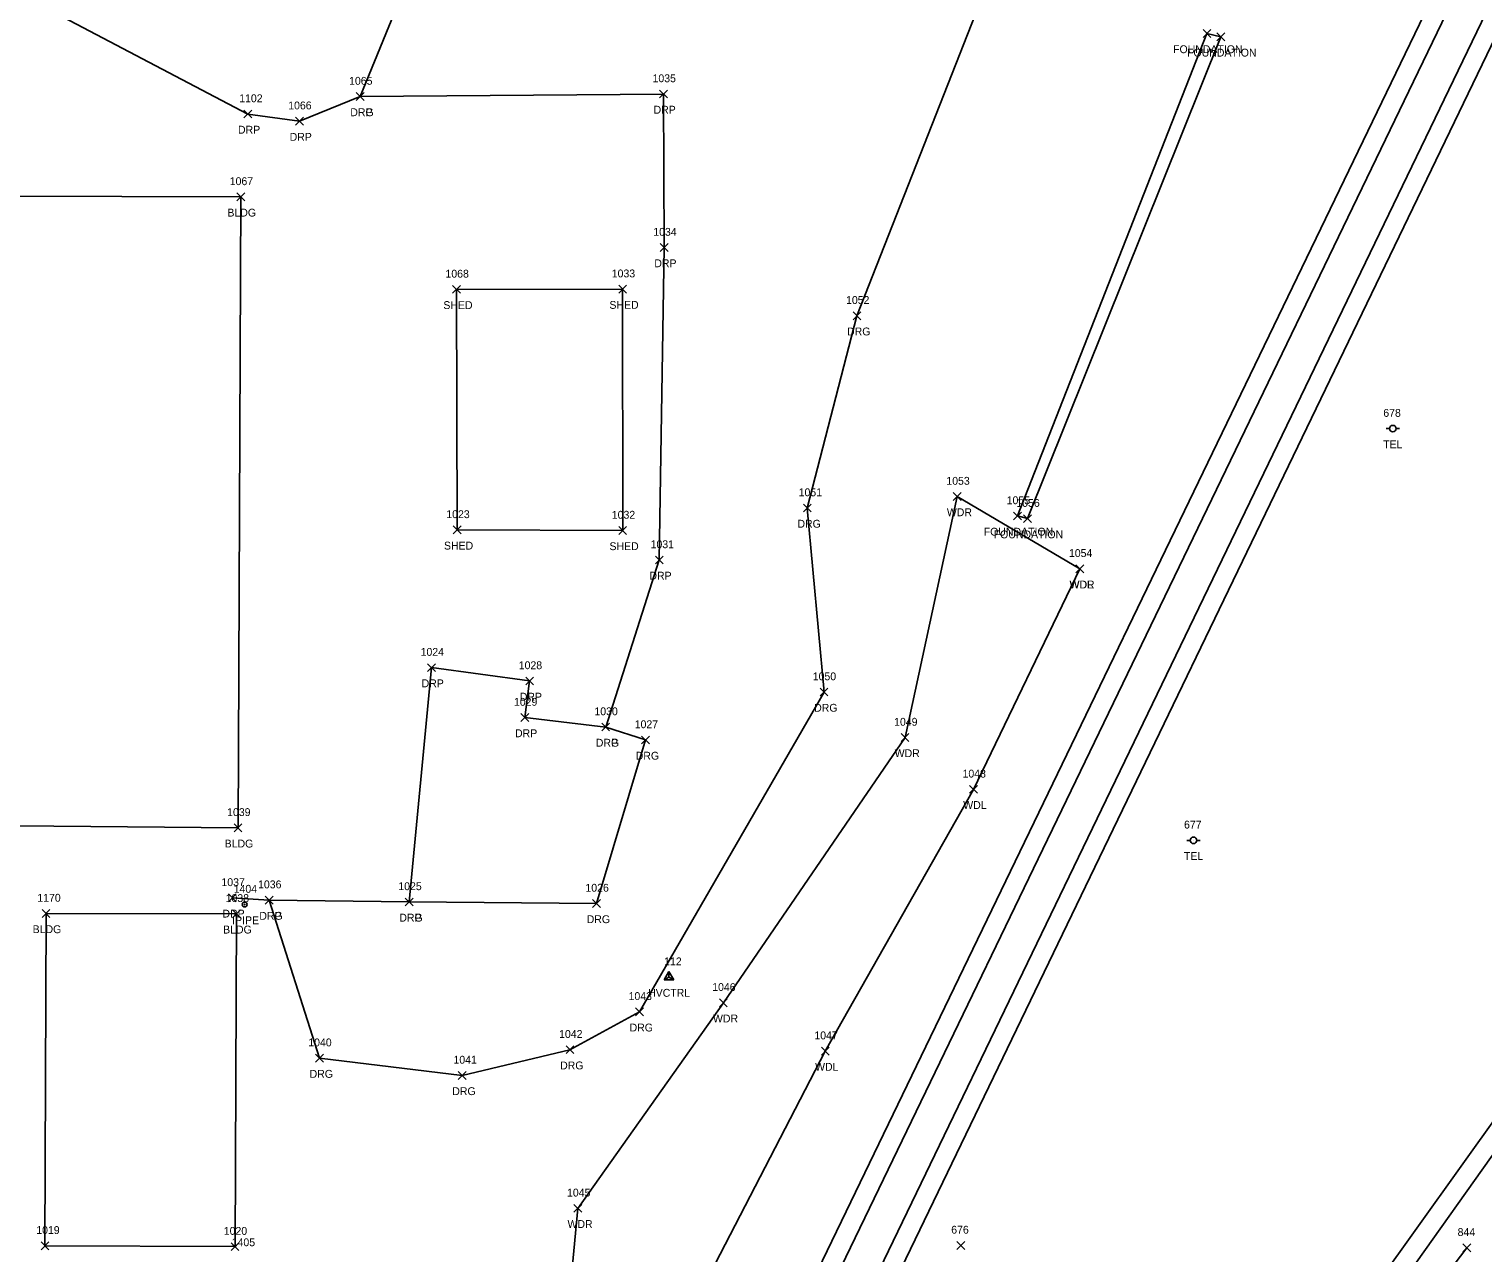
# Model space of a CAD drawing. Extents: x 1767353 to 1772625, y 740790 to 747702.
# Drawn here: x 1770255.6 to 1770625.6, y 742669.5 to 742981 of the extents above; entities that cross this region are included whole.
import ezdxf

# ---------------------------------------------------------------- set-up
doc = ezdxf.new("R2010")
doc.units = 0
for name, color, linetype in [('C_A', 7, 'Continuous'), ('C_I', 7, 'Continuous'), ('CPSM', 7, 'Continuous'), ('L_A', 7, 'Continuous'), ('L_I', 7, 'Continuous'), ('L_TIC', 7, 'Continuous'), ('LAWA', 7, 'Continuous'), ('LBC', 7, 'Continuous'), ('M_A', 7, 'Continuous'), ('M_I', 7, 'Continuous'), ('MPIP', 7, 'Continuous'), ('R_A', 7, 'Continuous'), ('R_I', 7, 'Continuous'), ('R_TIC', 7, 'Continuous'), ('RDG', 7, 'Continuous'), ('RDP', 7, 'Continuous'), ('RR', 7, 'Continuous'), ('U_A', 7, 'Continuous'), ('U_I', 7, 'Continuous'), ('UP', 7, 'Continuous')]:
    doc.layers.add(name, color=color, linetype=linetype)

msp = doc.modelspace()

# ---------------------------------------------------------------- linework, layer by layer
at = {"layer": 'CPSM'}
for p, q in [((1770417.21, 742738.98), (1770418.46, 742741.14)), ((1770417.21, 742738.98), (1770418.46, 742739.7)), ((1770419.71, 742738.98), (1770418.46, 742741.14)), ((1770418.46, 742739.7), (1770418.46, 742741.14)), ((1770418.46, 742739.7), (1770418.46, 742739.7)), ((1770418.46, 742739.7), (1770419.71, 742738.98)), ((1770417.21, 742738.98), (1770419.71, 742738.98))]:
    msp.add_line(p, q, dxfattribs=at)
at = {"layer": 'L_TIC'}
for points in [[(1770554.38, 742978.86), (1770556.38, 742980.86)], [(1770556.38, 742978.86), (1770554.38, 742980.86)], [(1770557.94, 742977.99), (1770559.94, 742979.99)], [(1770559.94, 742977.99), (1770557.94, 742979.99)], [(1770308.49, 742937.27), (1770310.49, 742939.27)], [(1770310.49, 742937.27), (1770308.49, 742939.27)], [(1770363.4, 742913.73), (1770365.4, 742915.73)], [(1770365.4, 742913.73), (1770363.4, 742915.73)], [(1770405.67, 742913.79), (1770407.67, 742915.79)], [(1770407.67, 742913.79), (1770405.67, 742915.79)], [(1770490.83, 742861.01), (1770492.83, 742863.01)], [(1770492.83, 742861.01), (1770490.83, 742863.01)], [(1770506.18, 742856.06), (1770508.18, 742858.06)], [(1770508.18, 742856.06), (1770506.18, 742858.06)], [(1770363.56, 742852.52), (1770365.56, 742854.52)], [(1770365.56, 742852.52), (1770363.56, 742854.52)], [(1770405.68, 742852.37), (1770407.68, 742854.37)], [(1770407.68, 742852.37), (1770405.68, 742854.37)], [(1770508.71, 742855.38), (1770510.71, 742857.38)], [(1770510.71, 742855.38), (1770508.71, 742857.38)], [(1770522.03, 742842.62), (1770524.03, 742844.62)], [(1770524.03, 742842.62), (1770522.03, 742844.62)], [(1770522.03, 742842.62), (1770524.03, 742844.62)], [(1770524.03, 742842.62), (1770522.03, 742844.62)], [(1770477.55, 742799.68), (1770479.55, 742801.68)], [(1770479.55, 742799.68), (1770477.55, 742801.68)], [(1770494.95, 742786.49), (1770496.95, 742788.49)], [(1770496.95, 742786.49), (1770494.95, 742788.49)], [(1770307.79, 742776.69), (1770309.79, 742778.69)], [(1770309.79, 742776.69), (1770307.79, 742778.69)], [(1770258.92, 742754.89), (1770260.92, 742756.89)], [(1770260.92, 742754.89), (1770258.92, 742756.89)], [(1770307.4, 742754.8), (1770309.4, 742756.8)], [(1770309.4, 742754.8), (1770307.4, 742756.8)], [(1770431.3, 742732.17), (1770433.3, 742734.17)], [(1770433.3, 742732.17), (1770431.3, 742734.17)], [(1770457.24, 742719.87), (1770459.24, 742721.87)], [(1770459.24, 742719.87), (1770457.24, 742721.87)], [(1770394.28, 742679.85), (1770396.28, 742681.85)], [(1770396.28, 742679.85), (1770394.28, 742681.85)], [(1770258.64, 742670.32), (1770260.64, 742672.32)], [(1770260.64, 742670.32), (1770258.64, 742672.32)], [(1770307.02, 742670.11), (1770309.02, 742672.11)], [(1770309.02, 742670.11), (1770307.02, 742672.11)], [(1770491.76, 742670.41), (1770493.76, 742672.41)], [(1770493.76, 742670.41), (1770491.76, 742672.41)], [(1770620.54, 742669.81), (1770622.54, 742671.81)], [(1770622.54, 742669.81), (1770620.54, 742671.81)]]:
    msp.add_lwpolyline(points, dxfattribs=at)
at = {"layer": 'LAWA'}
for points in [[(1770306.48, 742507.29), (1770316.18, 742614.11), (1770369.05, 742611.22), (1770392.48, 742651.21), (1770395.28, 742680.85), (1770432.3, 742733.17), (1770478.55, 742800.68), (1770491.83, 742862.01), (1770523.03, 742843.62)], [(1770306.48, 742507.29), (1770329.16, 742496.59), (1770362.8, 742536.32), (1770458.24, 742720.87), (1770495.95, 742787.49), (1770523.03, 742843.62)]]:
    msp.add_lwpolyline(points, dxfattribs=at)
at = {"layer": 'LBC'}
for points in [[(1770507.18, 742857.06), (1770509.71, 742856.38), (1770558.94, 742978.99), (1770555.38, 742979.86)], [(1770555.38, 742979.86), (1770507.18, 742857.06)], [(1770309.49, 742938.27), (1770248.94, 742938.42)], [(1770308.79, 742777.69), (1770309.49, 742938.27)], [(1770364.56, 742853.52), (1770406.68, 742853.37), (1770406.67, 742914.79), (1770364.4, 742914.73)], [(1770364.4, 742914.73), (1770364.56, 742853.52)], [(1770224.34, 742778.43), (1770308.79, 742777.69)], [(1770259.92, 742755.89), (1770259.64, 742671.32)], [(1770259.64, 742671.32), (1770308.02, 742671.11), (1770308.4, 742755.8)], [(1770308.4, 742755.8), (1770259.92, 742755.89)], [(1770582.39, 742619.29), (1770621.54, 742670.81)]]:
    msp.add_lwpolyline(points, dxfattribs=at)
at = {"layer": 'MPIP'}
for radius in [0.625, 0.0833]:
    msp.add_circle((1770310.46, 742758.17), radius, dxfattribs=at)
at = {"layer": 'R_TIC'}
for points in [[(1770416.05, 742963.46), (1770418.05, 742965.46)], [(1770418.05, 742963.46), (1770416.05, 742965.46)], [(1770338.87, 742962.82), (1770340.87, 742964.82)], [(1770340.87, 742962.82), (1770338.87, 742964.82)], [(1770338.87, 742962.82), (1770340.87, 742964.82)], [(1770340.87, 742962.82), (1770338.87, 742964.82)], [(1770310.28, 742958.37), (1770312.28, 742960.37)], [(1770312.28, 742958.37), (1770310.28, 742960.37)], [(1770323.43, 742956.55), (1770325.43, 742958.55)], [(1770325.43, 742956.55), (1770323.43, 742958.55)], [(1770416.24, 742924.38), (1770418.24, 742926.38)], [(1770418.24, 742924.38), (1770416.24, 742926.38)], [(1770465.3, 742907.02), (1770467.3, 742909.02)], [(1770467.3, 742907.02), (1770465.3, 742909.02)], [(1770452.67, 742858.09), (1770454.67, 742860.09)], [(1770454.67, 742858.09), (1770452.67, 742860.09)], [(1770415, 742844.87), (1770417, 742846.87)], [(1770417, 742844.87), (1770415, 742846.87)], [(1770357.02, 742817.47), (1770359.02, 742819.47)], [(1770359.02, 742817.47), (1770357.02, 742819.47)], [(1770357.02, 742817.47), (1770359.02, 742819.47)], [(1770359.02, 742817.47), (1770357.02, 742819.47)], [(1770382, 742814.07), (1770384, 742816.07)], [(1770384, 742814.07), (1770382, 742816.07)], [(1770456.92, 742811.25), (1770458.92, 742813.25)], [(1770458.92, 742811.25), (1770456.92, 742813.25)], [(1770380.79, 742804.76), (1770382.79, 742806.76)], [(1770382.79, 742804.76), (1770380.79, 742806.76)], [(1770401.35, 742802.35), (1770403.35, 742804.35)], [(1770403.35, 742802.35), (1770401.35, 742804.35)], [(1770401.35, 742802.35), (1770403.35, 742804.35)], [(1770403.35, 742802.35), (1770401.35, 742804.35)], [(1770411.51, 742799.05), (1770413.51, 742801.05)], [(1770413.51, 742799.05), (1770411.51, 742801.05)], [(1770306.33, 742758.87), (1770308.33, 742760.87)], [(1770308.33, 742758.87), (1770306.33, 742760.87)], [(1770315.71, 742758.3), (1770317.71, 742760.3)], [(1770317.71, 742758.3), (1770315.71, 742760.3)], [(1770315.71, 742758.3), (1770317.71, 742760.3)], [(1770317.71, 742758.3), (1770315.71, 742760.3)], [(1770351.35, 742757.83), (1770353.35, 742759.83)], [(1770353.35, 742757.83), (1770351.35, 742759.83)], [(1770351.35, 742757.83), (1770353.35, 742759.83)], [(1770353.35, 742757.83), (1770351.35, 742759.83)], [(1770399.03, 742757.44), (1770401.03, 742759.44)], [(1770401.03, 742757.44), (1770399.03, 742759.44)], [(1770409.95, 742729.87), (1770411.95, 742731.87)], [(1770411.95, 742729.87), (1770409.95, 742731.87)], [(1770392.27, 742720.22), (1770394.27, 742722.22)], [(1770394.27, 742720.22), (1770392.27, 742722.22)], [(1770328.52, 742718.08), (1770330.52, 742720.08)], [(1770330.52, 742718.08), (1770328.52, 742720.08)], [(1770364.82, 742713.67), (1770366.82, 742715.67)], [(1770366.82, 742713.67), (1770364.82, 742715.67)]]:
    msp.add_lwpolyline(points, dxfattribs=at)
at = {"layer": 'RDG'}
for points in [[(1770316.71, 742759.3), (1770329.52, 742719.08), (1770365.82, 742714.67), (1770393.27, 742721.22), (1770410.95, 742730.87), (1770457.92, 742812.25), (1770453.67, 742859.09), (1770466.3, 742908.02), (1770510.52, 743020.67), (1770407.29, 743051.18), (1770374.22, 743047.8), (1770339.87, 742963.82)], [(1770352.35, 742758.83), (1770400.03, 742758.44), (1770412.51, 742800.05), (1770402.35, 742803.35)]]:
    msp.add_lwpolyline(points, dxfattribs=at)
at = {"layer": 'RDP'}
for points in [[(1770358.02, 742818.47), (1770383, 742815.07), (1770381.79, 742805.76), (1770402.35, 742803.35), (1770416, 742845.87), (1770417.24, 742925.38), (1770417.05, 742964.46), (1770339.87, 742963.82), (1770324.43, 742957.55), (1770311.28, 742959.37), (1770250.85, 742991.18)], [(1770358.02, 742818.47), (1770352.35, 742758.83), (1770316.71, 742759.3), (1770307.33, 742759.87)]]:
    msp.add_lwpolyline(points, dxfattribs=at)
at = {"layer": 'RR'}
for points in [[(1770221.78, 741982.04), (1770226.9, 742005.14), (1770231.58, 742026.58), (1770238.97, 742057.62), (1770247.46, 742091.31), (1770255.17, 742120.86), (1770262.38, 742147.12), (1770270.79, 742177.04), (1770278.58, 742203.25), (1770285.57, 742226.22), (1770292.18, 742247.12), (1770303.7, 742282.6), (1770315.3, 742316.87), (1770330.35, 742359.31), (1770344.25, 742396.26), (1770362.68, 742444.08), (1770381.25, 742488.48), (1770399.89, 742531.75), (1770427.72, 742593.02), (1770459.92, 742661.06), (1770775.2, 743314.07), (1770996.39, 743772.66), (1771192.02, 744177.67), (1771329.71, 744462.72)], [(1770217.88, 741982.89), (1770224.63, 742006.05), (1770231.58, 742026.58), (1770242.49, 742057.3), (1770253.86, 742089.03), (1770263.22, 742117.76), (1770271, 742143.83), (1770279.57, 742174.49), (1770286.79, 742199.43), (1770293.9, 742223.08), (1770300.84, 742244.95), (1770311.67, 742279.15), (1770323.34, 742314.32), (1770337.98, 742356.11), (1770351.9, 742393.8), (1770370.52, 742441.44), (1770388.76, 742485.07), (1770407.79, 742528.71), (1770435.51, 742589.24), (1770468.44, 742657.89), (1770783.17, 743309.95), (1771004.51, 743768.91), (1771200.35, 744174.24), (1771337.45, 744458.43)], [(1770217.02, 741983.21), (1770222.11, 742006.18), (1770226.99, 742028.12), (1770234.33, 742059.23), (1770242.65, 742092.71), (1770250.33, 742121.94), (1770257.59, 742148.49), (1770265.95, 742178.19), (1770273.77, 742204.67), (1770280.68, 742227.53), (1770287.46, 742248.27), (1770299.11, 742284.6), (1770310.51, 742317.94), (1770325.96, 742361.53), (1770339.5, 742397.74), (1770358.03, 742445.88), (1770376.8, 742490.97), (1770395.2, 742533.35), (1770423.54, 742595.68), (1770455.2, 742662.62), (1770770.92, 743316.68), (1770991.9, 743774.87)], [(1770222.72, 741981.76), (1770229.32, 742004.36), (1770235.77, 742023.83), (1770247.09, 742055.41), (1770258.52, 742087.39), (1770268.11, 742116.55), (1770275.73, 742142.21), (1770291.55, 742198.01), (1770296.52, 742214.73), (1770305.48, 742243.41), (1770316.35, 742277.3), (1770328.03, 742312.86), (1770342.4, 742354.07), (1770356.59, 742392.13), (1770375.3, 742439.98), (1770392.87, 742482.18), (1770412.29, 742526.82), (1770439.88, 742586.94), (1770472.88, 742655.84), (1770787.34, 743307.49), (1771008.99, 743766.96)], [(1770271.52, 742143.69), (1770280.69, 742174.18), (1770289.74, 742198.6), (1770296.52, 742214.73), (1770308.93, 742241.95), (1770324.06, 742274.04), (1770340.68, 742308.04), (1770360.15, 742345.64), (1770381.03, 742382.61), (1770407.02, 742424.16), (1770425.18, 742450.58), (1770450.26, 742483.52), (1770473.18, 742510.79), (1770518.15, 742562.81), (1770572.7, 742627.85), (1770598.36, 742661.22), (1770630.52, 742706.14), (1770655.11, 742743.9), (1770674.5, 742775.55), (1770683.79, 742791.45), (1770706.15, 742833.16), (1770731.07, 742883.64), (1770775.22, 742979.87)], [(1770275.73, 742142.21), (1770285.7, 742173.47), (1770294.36, 742196.77), (1770301.28, 742213.26), (1770313.54, 742240.29), (1770328.52, 742271.98), (1770345.02, 742305.68), (1770363.97, 742342.43), (1770385.56, 742380.58), (1770410.92, 742420.89), (1770428.56, 742446.86), (1770454.89, 742481.33), (1770476.7, 742507.31), (1770522.14, 742559.86), (1770576.25, 742624.32), (1770602.26, 742658.04), (1770634.11, 742702.9), (1770659.93, 742742.21), (1770678.83, 742773.23), (1770687.73, 742788.35), (1770710.35, 742830.29), (1770735.06, 742880.72), (1770779.65, 742978.02)]]:
    msp.add_lwpolyline(points, dxfattribs=at)
at = {"layer": 'UP'}
for p, q in [((1770601.03, 742879.29), (1770601.85, 742879.29)), ((1770602.68, 742879.3), (1770602.68, 742879.3)), ((1770604.35, 742879.3), (1770603.52, 742879.3)), ((1770603.52, 742879.3), (1770603.52, 742879.3)), ((1770604.35, 742879.3), (1770604.35, 742879.3)), ((1770550.3, 742774.5), (1770551.13, 742774.5)), ((1770551.96, 742774.51), (1770551.96, 742774.51)), ((1770553.63, 742774.51), (1770552.8, 742774.51)), ((1770552.8, 742774.51), (1770552.8, 742774.51)), ((1770553.63, 742774.51), (1770553.63, 742774.51))]:
    msp.add_line(p, q, dxfattribs=at)
for centre in [(1770602.68, 742879.3), (1770551.96, 742774.51)]:
    msp.add_circle(centre, 0.833, dxfattribs=at)

# ---------------------------------------------------------------- texts
at = {"layer": 'C_A'}
msp.add_text('HVCTRL', height=2, dxfattribs=at).set_placement((1770413.15, 742734.7))
at = {"layer": 'C_I'}
msp.add_text('112', height=2, dxfattribs=at).set_placement((1770417.23, 742742.7))
at = {"layer": 'L_A'}
for s, p in [('FOUNDATION', (1770546.77, 742974.86)), ('FOUNDATION', (1770550.33, 742973.99)), ('BLDG', (1770306.08, 742933.27)), ('SHED', (1770361.04, 742909.73)), ('SHED', (1770403.3, 742909.79)), ('WDR', (1770489.19, 742857.01)), ('FOUNDATION', (1770498.58, 742852.06)), ('SHED', (1770361.2, 742848.52)), ('SHED', (1770403.32, 742848.37)), ('FOUNDATION', (1770501.11, 742851.38)), ('WDR', (1770520.39, 742838.62)), ('WDL', (1770520.45, 742838.62)), ('WDR', (1770475.91, 742795.68)), ('WDL', (1770493.36, 742782.49)), ('BLDG', (1770305.38, 742772.69)), ('BLDG', (1770256.51, 742750.89)), ('BLDG', (1770304.99, 742750.8)), ('WDR', (1770429.66, 742728.17)), ('WDL', (1770455.66, 742715.87)), ('WDR', (1770392.64, 742675.85))]:
    msp.add_text(s, height=2, dxfattribs=at).set_placement(p)
at = {"layer": 'L_I'}
for s, p in [('1067', (1770306.67, 742941.27)), ('1068', (1770361.58, 742917.73)), ('1033', (1770403.9, 742917.79)), ('1053', (1770489.06, 742865.01)), ('1055', (1770504.41, 742860.06)), ('1056', (1770506.88, 742859.38)), ('1023', (1770361.79, 742856.52)), ('1032', (1770403.91, 742856.37)), ('1054', (1770520.26, 742846.62)), ('1054', (1770520.26, 742846.62)), ('1049', (1770475.77, 742803.68)), ('1048', (1770493.18, 742790.49)), ('1039', (1770306.01, 742780.69)), ('1170', (1770257.7, 742758.89)), ('1038', (1770305.63, 742758.8)), ('1046', (1770429.47, 742736.17)), ('1047', (1770455.47, 742723.87)), ('1045', (1770392.51, 742683.85)), ('1019', (1770257.43, 742674.32)), ('676', (1770490.3, 742674.41)), ('1020', (1770305.16, 742674.11)), ('844', (1770619.18, 742673.81))]:
    msp.add_text(s, height=2, dxfattribs=at).set_placement(p)
at = {"layer": 'M_A'}
msp.add_text('IPIPE', height=2, dxfattribs=at).set_placement((1770307.29, 742753.17))
at = {"layer": 'M_I'}
for s, p in [('1404', (1770307.68, 742761.17)), ('1405', (1770307.17, 742671.21))]:
    msp.add_text(s, height=2, dxfattribs=at).set_placement(p)
at = {"layer": 'R_A'}
for s, p in [('DRP', (1770414.54, 742959.46)), ('DRG', (1770337.36, 742958.82)), ('DRP', (1770337.36, 742958.82)), ('DRP', (1770308.77, 742954.37)), ('DRP', (1770321.92, 742952.55)), ('DRP', (1770414.73, 742920.38)), ('DRG', (1770463.79, 742903.02)), ('DRG', (1770451.16, 742854.09)), ('DRP', (1770413.49, 742840.87)), ('DRP', (1770355.51, 742813.47)), ('DRP', (1770355.51, 742813.47)), ('DRP', (1770380.49, 742810.07)), ('DRG', (1770455.41, 742807.25)), ('DRP', (1770379.28, 742800.76)), ('DRG', (1770399.84, 742798.35)), ('DRP', (1770399.84, 742798.35)), ('DRG', (1770410, 742795.05)), ('DRP', (1770304.82, 742754.87)), ('DRG', (1770314.2, 742754.3)), ('DRP', (1770314.2, 742754.3)), ('DRG', (1770349.84, 742753.83)), ('DRP', (1770349.84, 742753.83)), ('DRG', (1770397.52, 742753.44)), ('DRG', (1770408.44, 742725.87)), ('DRG', (1770390.76, 742716.22)), ('DRG', (1770327, 742714.08)), ('DRG', (1770363.31, 742709.67))]:
    msp.add_text(s, height=2, dxfattribs=at).set_placement(p)
at = {"layer": 'R_I'}
for s, p in [('1065', (1770337.05, 742966.82)), ('1065', (1770337.05, 742966.82)), ('1035', (1770414.28, 742967.46)), ('1102', (1770309.08, 742962.37)), ('1066', (1770321.56, 742960.55)), ('1034', (1770414.47, 742928.38)), ('1052', (1770463.53, 742911.02)), ('1051', (1770451.47, 742862.09)), ('1031', (1770413.79, 742848.87)), ('1024', (1770355.25, 742821.47)), ('1024', (1770355.25, 742821.47)), ('1028', (1770380.23, 742818.07)), ('1050', (1770455.06, 742815.25)), ('1029', (1770379.01, 742808.76)), ('1030', (1770399.49, 742806.35)), ('1030', (1770399.49, 742806.35)), ('1027', (1770409.74, 742803.05)), ('1037', (1770304.56, 742762.87)), ('1036', (1770313.88, 742762.3)), ('1036', (1770313.88, 742762.3)), ('1025', (1770349.58, 742761.83)), ('1025', (1770349.58, 742761.83)), ('1026', (1770397.2, 742761.44)), ('1043', (1770408.18, 742733.87)), ('1042', (1770390.5, 742724.22)), ('1040', (1770326.66, 742722.08)), ('1041', (1770363.62, 742717.67))]:
    msp.add_text(s, height=2, dxfattribs=at).set_placement(p)
at = {"layer": 'U_A'}
for p in [(1770600.24, 742874.3), (1770549.52, 742769.51)]:
    msp.add_text('TEL', height=2, dxfattribs=at).set_placement(p)
at = {"layer": 'U_I'}
for s, p in [('678', (1770600.27, 742882.3)), ('677', (1770549.55, 742777.51))]:
    msp.add_text(s, height=2, dxfattribs=at).set_placement(p)

doc.saveas('drawing.dxf')
